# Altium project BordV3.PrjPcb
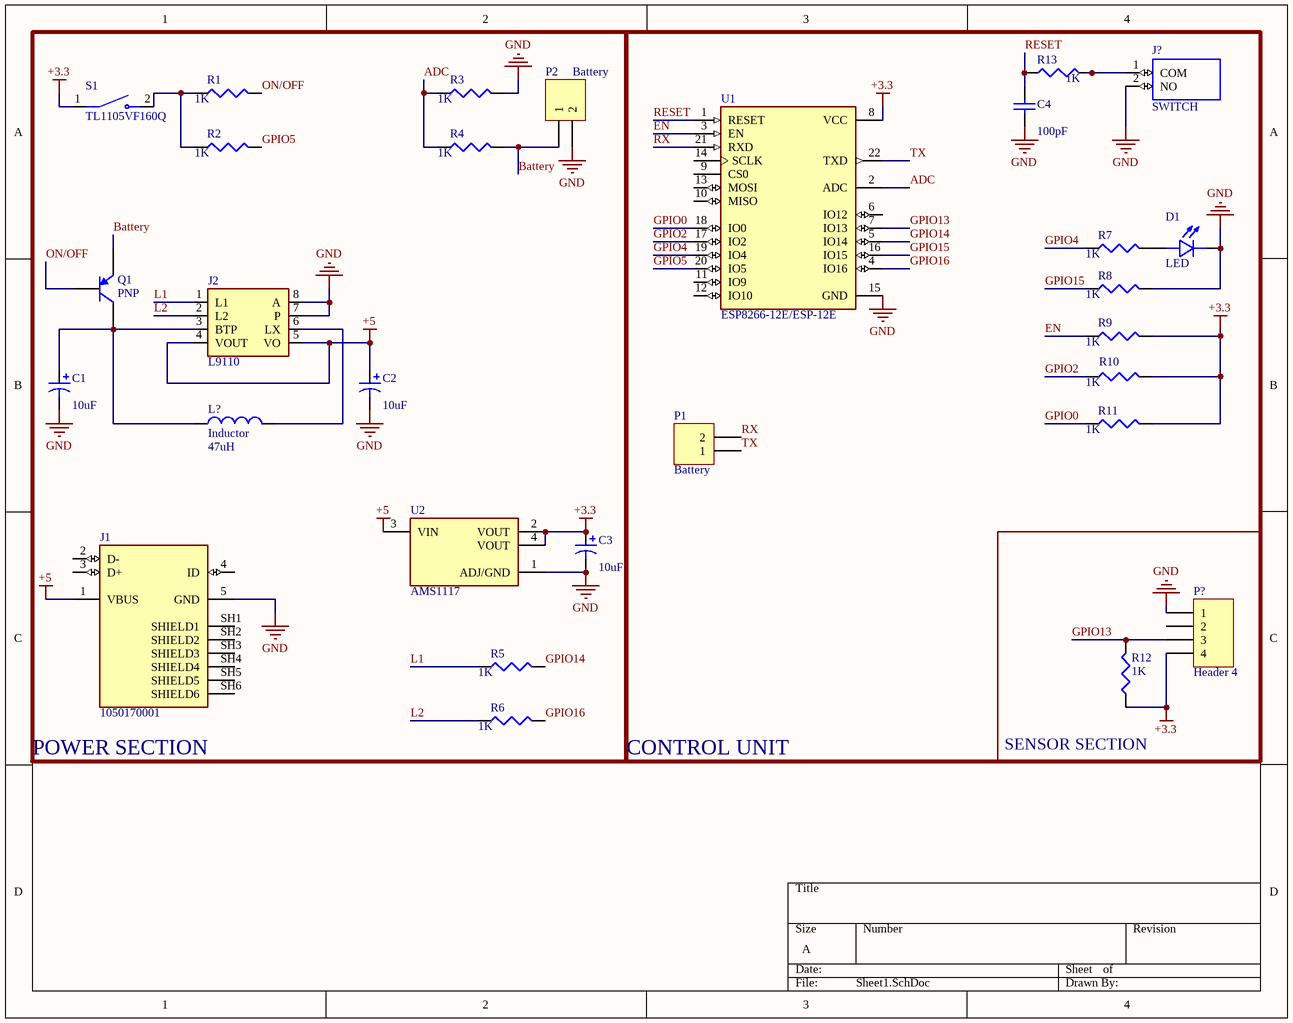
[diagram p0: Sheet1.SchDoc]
1 sheet, 29 parts. Net scope: global (net labels, ports and power ports of the same name join across sheets).
Board file: PCB1.PcbDoc

## Sheet Sheet1.SchDoc
size A; SheetNumber: 1; SheetTotal: 1

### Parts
C1  value 10uF  [1812]
C2  value 10uF  [1812]
C3  value 10uF  [1812]
C4  value 100pF  [C1206]
D1  LED  [LEDC3216X120N]
J1  1050170001  [MOLEX_1050170001]
J2  L9110  [SO-08]
J?  SWITCH  [PTS636SM25FSMTRLFS]
L?  Inductor  value 47uH  [INDC4532]
P1  Battery  [HDR1X2]
P2  Battery  [HDR1X2]
P?  Header 4  [HDR1X4]
Q1  PNP  [SOT-23B_N]
R1  value 1K  [14-1210]
R2  value 1K  [14-1210]
R3  value 1K  [14-1210]
R4  value 1K  [14-1210]
R5  value 1K  [14-1210]
R6  value 1K  [14-1210]
R7  value 1K  [14-1210]
R8  value 1K  [14-1210]
R9  value 1K  [14-1210]
R10  value 1K  [14-1210]
R11  value 1K  [14-1210]
R12  value 1K  [14-1210]
R13  value 1K  [14-1210]
S1  TL1105VF160Q  [SW_TL1105VF160Q]
U1  ESP8266-12E/ESP-12E  [XCVR_ESP8266-12E/ESP-12E]
U2  AMS1117  [SOT229P700X180-4N]

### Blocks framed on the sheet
POWER SECTION: C1-C3 J1 J2 L? P2 Q1 R1-R6 S1 U2
CONTROL UNIT: C4 D1 J? P1 R7-R11 R13 U1
SENSOR SECTION: P? R12

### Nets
+3.3: C3.1 P?.4 R9.2 R10.2 R11.2 R12.1 S1.1 U1.8(VCC) U2.2(VOUT) U2.4(VOUT)
+5: C2.1 J1.1(VBUS) J2.4(VOUT) J2.5(VO) U2.3(VIN)
GND: C1.2 C2.2 C3.2 C4.1 D1.NEG J1.5(GND) J2.7(P) J2.8(A) J?.2(NO) P2.2 P?.1 R3.2 R8.2 U1.15(GND) U2.1(ADJ/GND)
ADC: R3.1 R4.1 U1.2(ADC)
Battery: P2.1 Q1.3(E) R4.2
EN: R9.1 U1.3(EN)
GPIO0: R11.1 U1.18(IO0)
GPIO2: R10.1 U1.17(IO2)
GPIO4: R7.1 U1.19(IO4)
GPIO5: R2.2 U1.20(IO5)
GPIO13: P?.3 R12.2 U1.7(IO13)
GPIO14: R5.2 U1.5(IO14)
GPIO15: R8.1 U1.16(IO15)
GPIO16: R6.2 U1.4(IO16)
L1: J2.1(L1) R5.1
L2: J2.2(L2) R6.1
ON/OFF: Q1.2(B) R1.2
RESET: C4.2 R13.1 U1.1(RESET)
RX: P1.2 U1.21(RXD)
TX: P1.1 U1.22(TXD)
NetC1_1: C1.1 J2.3(BTP) L?.1 Q1.1(C)
NetD1_POS: D1.POS R7.2
NetJ2_6: J2.6(LX) L?.2
NetJ?_1: J?.1(COM) R13.2
NetR1_1: R1.1 R2.1 S1.2

Not connected (* = marked no-connect by the designer): J1 2(D-) 3(D+) 4(ID) SH1(SHIELD1) SH2(SHIELD2) SH3(SHIELD3) SH4(SHIELD4) SH5(SHIELD5) SH6(SHIELD6); P? 2; U1 6(IO12) 9(CS0) 10(MISO) 11(IO9) 12(IO10) 13(MOSI) 14(SCLK)

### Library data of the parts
C1-C3 = Cap Pol3: Polarized Capacitor (Surface Mount)
C4 = Cap Semi: Capacitor (Semiconductor SIM Model)
D1 = LHN974_RED_LED_1206: 2.6 V Red LED SMD; MF: Osram; MP: LHN974 RED LED 1206
J1 = 1050170001: USB - micro B USB 2.0 Receptacle Connector 5 Position Surface Mount, Right Angle; Through Hole; MF: Molex
J2 = L9110: Motor control driver chip; MF: Asic; MP: L9110 (SOP-8)
J? = PTS636_SM25F_SMTR_LFS: Tactile Switch SPST-NO Top Actuated Surface Mount; MF: C&K; MP: PTS636 SM25F SMTR LFS
L? = Inductor: Code_IEC: 1005
P1 P2 = Header 2: Header, 2-Pin
P? = Header 4: Header, 4-Pin
Q1 = PNP: PNP Bipolar Transistor
R1-R13 = Res3: Resistor
S1 = TL1105VF160Q: Tactile Switch, TL1105 Series, SPST-NO, 3.85mm Side Actuated, 0.05A, 12VDC, PC ¦ E-Switch TL1105VF160Q
U1 = ESP8266-12E/ESP-12E: This WiFi module has a 32-bit MCU micro and clock speeds supporting 80 MHz or 160 MHz. Supports the RTOS and integrated Wi-Fi MAC/BB/RF/PA/LNA, and has an on-board antenna.; MF: AI-Thinker
U2 = AMS1117: 1A LOW DROPOUT VOLTAGE REGULATOR SOT-223; MF: Advanced Monolithic Systems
